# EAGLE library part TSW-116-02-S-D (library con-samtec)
THROUGH-HOLE .025" SQ POST HEADER Source: Samtec TSW.pdf
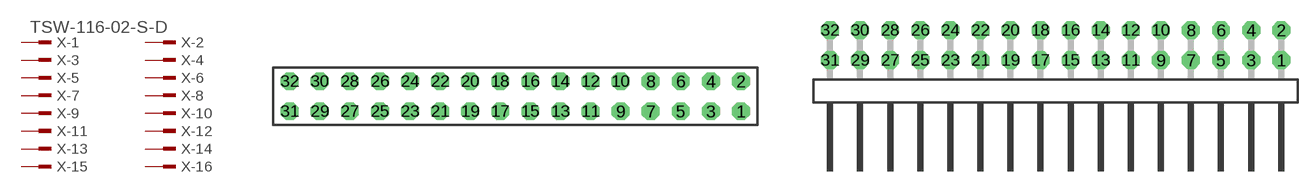
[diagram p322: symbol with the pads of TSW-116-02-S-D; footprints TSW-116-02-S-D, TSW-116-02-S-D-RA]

Designator prefix X; gates -1=MPINV -2=MPIN -3=MPIN -4=MPIN -5=MPIN -6=MPIN -7=MPIN -8=MPIN -9=MPIN -10=MPIN -11=MPIN -12=MPIN -13=MPIN -14=MPIN -15=MPIN -16=MPIN -17=MPIN -18=MPIN -19=MPIN -20=MPIN -21=MPIN -22=MPIN -23=MPIN -24=MPIN -25=MPIN -26=MPIN -27=MPIN -28=MPIN -29=MPIN -30=MPIN -31=MPIN -32=MPIN

## TSW-116-02-S-D (OC_FARNELL: unknown; OC_NEWARK: unknown)  [TSW-116-02-S-D]
1  -1:1  pas
2  -2:1  pas
3  -3:1  pas
4  -4:1  pas
5  -5:1  pas
6  -6:1  pas
7  -7:1  pas
8  -8:1  pas
9  -9:1  pas
10  -10:1  pas
11  -11:1  pas
12  -12:1  pas
13  -13:1  pas
14  -14:1  pas
15  -15:1  pas
16  -16:1  pas
17  -17:1  pas
18  -18:1  pas
19  -19:1  pas
20  -20:1  pas
21  -21:1  pas
22  -22:1  pas
23  -23:1  pas
24  -24:1  pas
25  -25:1  pas
26  -26:1  pas
27  -27:1  pas
28  -28:1  pas
29  -29:1  pas
30  -30:1  pas
31  -31:1  pas
32  -32:1  pas

## TSW-116-02-S-D-RA (OC_FARNELL: unknown; OC_NEWARK: unknown)  [TSW-116-02-S-D-RA]
Pads as for TSW-116-02-S-D

## Footprint TSW-116-02-S-D (pad centres in mm)
THROUGH-HOLE .025" SQ POST HEADER Source: Samtec TSW.pdf
drill 1 pad 1.5 octagon: 1 19.05,-1.27; 2 19.05,1.27; 3 16.51,-1.27; 4 16.51,1.27; 5 13.97,-1.27; 6 13.97,1.27; 7 11.43,-1.27; 8 11.43,1.27; 9 8.89,-1.27; 10 8.89,1.27; 11 6.35,-1.27; 12 6.35,1.27; 13 3.81,-1.27; 14 3.81,1.27; 15 1.27,-1.27; 16 1.27,1.27; 17 -1.27,-1.27; 18 -1.27,1.27; 19 -3.81,-1.27; 20 -3.81,1.27; 21 -6.35,-1.27; 22 -6.35,1.27; 23 -8.89,-1.27; 24 -8.89,1.27; 25 -11.43,-1.27; 26 -11.43,1.27; 27 -13.97,-1.27; 28 -13.97,1.27; 29 -16.51,-1.27; 30 -16.51,1.27; 31 -19.05,-1.27; 32 -19.05,1.27

## Footprint TSW-116-02-S-D-RA (pad centres in mm)
THROUGH-HOLE .025" SQ POST HEADER Source: Samtec TSW.pdf
drill 1 pad 1.5 octagon: 1 19.05,1.524; 2 19.05,4.064; 3 16.51,1.524; 4 16.51,4.064; 5 13.97,1.524; 6 13.97,4.064; 7 11.43,1.524; 8 11.43,4.064; 9 8.89,1.524; 10 8.89,4.064; 11 6.35,1.524; 12 6.35,4.064; 13 3.81,1.524; 14 3.81,4.064; 15 1.27,1.524; 16 1.27,4.064; 17 -1.27,1.524; 18 -1.27,4.064; 19 -3.81,1.524; 20 -3.81,4.064; 21 -6.35,1.524; 22 -6.35,4.064; 23 -8.89,1.524; 24 -8.89,4.064; 25 -11.43,1.524; 26 -11.43,4.064; 27 -13.97,1.524; 28 -13.97,4.064; 29 -16.51,1.524; 30 -16.51,4.064; 31 -19.05,1.524; 32 -19.05,4.064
